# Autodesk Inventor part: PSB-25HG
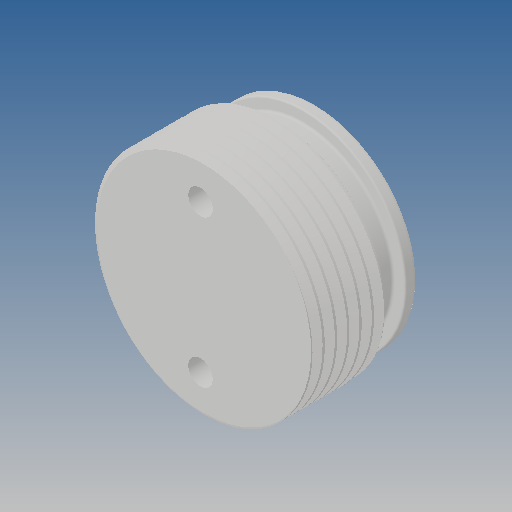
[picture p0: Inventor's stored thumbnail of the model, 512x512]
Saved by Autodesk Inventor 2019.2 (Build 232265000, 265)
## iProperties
Created: 2010-02
Part Number: PSB-25HG
Material: Ogólny
Document SubType Name: Modeling
Designer: CADENGINEERING4
Density: 1 g/cm^3
Appearance: Domyślna
Author: CADENGINEERING4
Revision Number: 1LAST_VERSION
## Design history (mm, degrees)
feature "Baza1"
node "Bryła1"
